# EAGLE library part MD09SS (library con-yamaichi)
YAMAICHI CONNECTOR
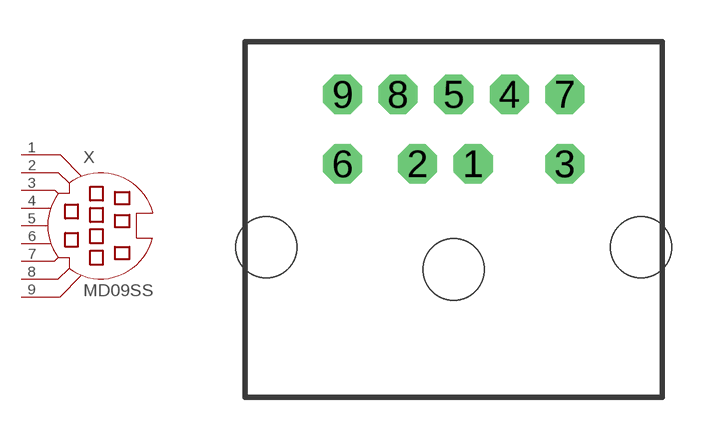
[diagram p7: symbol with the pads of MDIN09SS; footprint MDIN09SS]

Designator prefix X

## MD09SS (OC_FARNELL: unknown; OC_NEWARK: unknown)  [MDIN09SS]
1  1  pas
2  2  pas
3  3  pas
4  4  pas
5  5  pas
6  6  pas
7  7  pas
8  8  pas
9  9  pas

## Footprint MDIN09SS (pad centres in mm)
Mini Din YAMAICHI CONNECTOR
drill 0.9 octagon: 1 0.7,8.5; 2 -1.3,8.5; 3 4,8.5; 4 2,11; 5 0,11; 6 -4,8.5; 7 4,11; 8 -2,11; 9 -4,11
hole 2.2 at -6.75,5.5
hole 2.2 at 0,4.7
hole 2.2 at 6.75,5.5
